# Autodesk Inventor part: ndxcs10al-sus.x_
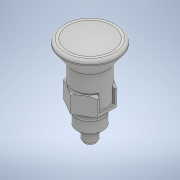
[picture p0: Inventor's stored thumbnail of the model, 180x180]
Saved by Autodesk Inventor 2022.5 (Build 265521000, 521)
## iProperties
Created: 2018-04
Part Number: ndxcs10al-sus.x_
Material: 一般
Document SubType Name: Modeling
Designer: imaocorp
Density: 1 g/cm^3
Appearance: 既定
Sending System: SOLIDWORKS 2016-2016286
MC: AMD64
MC_MODEL: AMD64 Family 21 Model 2 Stepping 0, AuthenticAMD
OS: Windows_NT
FRU: Parasolid Version 28.0, build 224,  7-29-2016
FORMAT: text
GUISE: transmit
KEY: ndxcs10al-sus
FILE: ndxcs10al-sus.x_t
DATE: Wed Apr 25 10:17:20 2018
Author: imaocorp
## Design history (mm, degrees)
feature "Base1"
node "ソリッド1"
